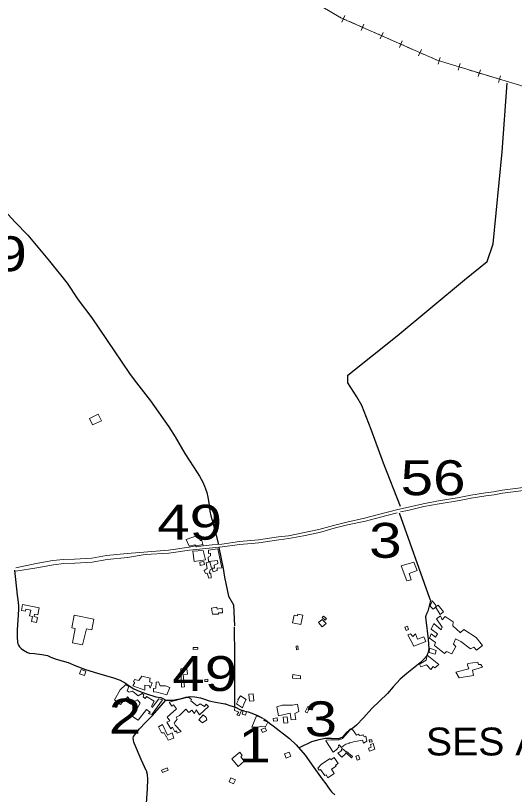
# Model space of a CAD drawing. Extents: x 476989 to 498418, y 4381813 to 4416555.
# Drawn here: x 486413 to 487128, y 4387137 to 4388253 of the extents above; entities that cross this region are included whole.
import ezdxf
from ezdxf.enums import TextEntityAlignment as Align

# ---------------------------------------------------------------- set-up
doc = ezdxf.new("R2010")
doc.units = 0
doc.header["$LTSCALE"] = 20
doc.linetypes.add('MEDIUM_DASHED', pattern=[4.5, 3, -1.5])
for name, color, linetype, lineweight in [('13', 7, 'Continuous', 13), ('34', 7, 'Continuous', 13), ('36', 7, 'Continuous', 13), ('47', 7, 'Continuous', 13), ('48', 7, 'MEDIUM_DASHED', 13), ('6', 7, 'Continuous', 25)]:
    doc.layers.add(name, color=color, linetype=linetype, lineweight=lineweight)
doc.layers.add('7', color=7, linetype='Continuous')

msp = doc.modelspace()

# ---------------------------------------------------------------- linework, layer by layer
at = {"layer": '34'}
for p, q in [((486884.69, 4388252.95), (486880.65, 4388243.8)), ((486891.82, 4388244.33), (486900.97, 4388240.29)), ((486905.53, 4388238.27), (486914.68, 4388234.23)), ((486912.12, 4388240.83), (486908.08, 4388231.68)), ((486919.25, 4388232.21), (486928.39, 4388228.17)), ((486932.96, 4388226.15), (486942.11, 4388222.11)), ((486939.55, 4388228.7), (486935.51, 4388219.55)), ((486946.68, 4388220.08), (486955.82, 4388216.04)), ((486960.39, 4388214.02), (486969.53, 4388209.98)), ((486966.98, 4388216.58), (486962.94, 4388207.43)), ((486974.11, 4388207.96), (486983.25, 4388203.92)), ((486987.82, 4388201.9), (486996.96, 4388197.86)), ((486994.41, 4388204.45), (486990.37, 4388195.3)), ((487001.54, 4388195.83), (487010.68, 4388191.79)), ((487021.4, 4388192.89), (487018.5, 4388183.32)), ((487029.52, 4388185.2), (487039.09, 4388182.29)), ((487043.86, 4388180.84), (487053.43, 4388177.94)), ((487050.1, 4388184.17), (487047.19, 4388174.6)), ((487058.22, 4388176.48), (487067.78, 4388173.58)), ((487072.56, 4388172.13), (487082.13, 4388169.22)), ((487078.8, 4388175.46), (487075.89, 4388165.89)), ((487086.91, 4388167.77), (487096.48, 4388164.86)), ((487101.25, 4388163.41), (487110.82, 4388160.51)), ((487107.49, 4388166.74), (487104.59, 4388157.17)), ((487115.61, 4388159.05), (487125.18, 4388156.15))]:
    msp.add_line(p, q, dxfattribs=at)
for points in [[(486520.9, 4388755.72), (486603, 4388633), (486612, 4388581), (486746, 4388393), (486776, 4388338), (486812, 4388290), (486879, 4388250), (487017, 4388189), (487152, 4388148), (487234, 4388140), (487360, 4387899), (487497, 4387717), (487531, 4387660), (487608, 4387440), (487634, 4387181), (487675, 4387065), (487547, 4387001), (487350, 4386921), (487175, 4386900), (487110, 4386912), (487380, 4386493), (487280.6, 4386441.97)], [(486878.15, 4388250.5), (486879, 4388250), (486887.25, 4388246.36)], [(487015.25, 4388189.77), (487017, 4388189), (487024.74, 4388186.65)]]:
    msp.add_lwpolyline(points, dxfattribs=at)
at = {"layer": '36'}
for points in [[(486964.24, 4387541.72), (486976.62, 4387544.44), (486997.64, 4387549.32), (487019.8, 4387553.44), (487049.13, 4387558.2), (487065.84, 4387561.49), (487086.71, 4387564.87), (487098.48, 4387566.27), (487110.55, 4387568.8), (487159.87, 4387575), (487190.84, 4387579.06), (487223.09, 4387583.7), (487249.79, 4387587.82), (487273.23, 4387590.72), (487282.06, 4387591.19), (487293.97, 4387593.33), (487302.49, 4387595.71), (487317.85, 4387602.66), (487349.41, 4387615.35), (487395.22, 4387635.1), (487449.89, 4387659.15), (487513.35, 4387686.84), (487513.66, 4387686.96)], [(486681.81, 4387493.08), (486694.64, 4387494.43), (486708.83, 4387495.72), (486733.93, 4387499.19), (486761.2, 4387501.8), (486789.75, 4387505.79), (486803.91, 4387507.68), (486824.62, 4387511.62), (486847.35, 4387516.42), (486868.27, 4387522.32), (486887.64, 4387527.27), (486913.13, 4387532.74), (486932.76, 4387537.91), (486960.47, 4387544.96), (486975.67, 4387548.51), (486996.79, 4387553.41), (487019.08, 4387557.56), (487048.39, 4387562.31), (487065.1, 4387565.6), (487086.13, 4387569.01), (487097.8, 4387570.4), (487109.95, 4387572.95), (487159.3, 4387579.14)], [(486598.9, 4387480.47), (486632.81, 4387482.84), (486662.41, 4387486.84), (486695.05, 4387490.27), (486709.31, 4387491.57), (486734.42, 4387495.04), (486761.69, 4387497.65), (486790.31, 4387501.65), (486804.58, 4387503.55), (486825.44, 4387507.52), (486848.35, 4387512.36), (486869.35, 4387518.28), (486888.6, 4387523.19), (486914.1, 4387528.67), (486933.81, 4387533.87), (486959.88, 4387540.27)], [(486632.38, 4387487), (486661.92, 4387490.99), (486681.28, 4387495)], [(486413.56, 4387461.76), (486442.85, 4387467.63), (486466.63, 4387471.94), (486482.05, 4387473.6), (486497.67, 4387474.12), (486522.37, 4387475.65), (486543.65, 4387479.24), (486573.11, 4387482.2), (486632.38, 4387487)], [(486413.64, 4387456.96), (486443.84, 4387461.83), (486467.47, 4387466.12), (486482.46, 4387467.73), (486497.95, 4387468.25), (486523.04, 4387469.8), (486544.43, 4387473.41), (486573.69, 4387476.35), (486598.9, 4387480.47)]]:
    msp.add_lwpolyline(points, dxfattribs=at)
at = {"layer": '47'}
for points in [[(486681.79, 4387493.07), (486672.16, 4387491.55), (486669.88, 4387494.66), (486662.05, 4387492.45), (486657.31, 4387501.97), (486675.11, 4387508.62), (486677.55, 4387500.93), (486679.72, 4387500.83)], [(486702.81, 4387488.86), (486689.51, 4387486.95), (486689.28, 4387481.93), (486692.44, 4387482.41), (486692.39, 4387478.88), (486688.91, 4387476.98), (486689.65, 4387470.82), (486702.2, 4387472.21), (486702.81, 4387467.63), (486697.75, 4387465.6), (486697.92, 4387461.17), (486693.79, 4387460.93), (486691.37, 4387470.42), (486686.02, 4387468.54), (486687.4, 4387460.65), (486683.39, 4387457.85), (486684.98, 4387453.7), (486687.83, 4387454.11), (486690.05, 4387446.65), (486693.36, 4387447.2), (486693.01, 4387453.96), (486690.46, 4387454.15), (486691.88, 4387458.93), (486694.82, 4387460.09), (486696.34, 4387455.94), (486701.85, 4387457.89), (486701.89, 4387461.04), (486708.65, 4387461.77)], [(486681.77, 4387486.46), (486685.26, 4387473.28), (486668.94, 4387470.89), (486666.9, 4387485.4)], [(486682.82, 4387470.77), (486676.87, 4387469.5), (486677.41, 4387464.84), (486683.66, 4387466.48)], [(486988.11, 4387457.61), (486976.94, 4387453.27), (486979.74, 4387444.23), (486973.64, 4387442.81), (486965.47, 4387464.47), (486983.7, 4387469.68)], [(487009.7, 4387414.31), (487006.96, 4387406.84), (487011.33, 4387402.58), (487015.65, 4387405.67), (487014.64, 4387408.39)], [(486423.14, 4387409.21), (486446.93, 4387404.29), (486444.89, 4387394.45), (486440.49, 4387395.32), (486439.77, 4387391.68), (486444.84, 4387390.63), (486443.34, 4387383.4), (486436.27, 4387384.85), (486437.68, 4387391.77), (486433.34, 4387392.62), (486435, 4387401.12), (486427.82, 4387402.49), (486427.27, 4387399.61), (486421.83, 4387400.62)], [(486693.57, 4387403.76), (486695.02, 4387395.26), (486703.65, 4387395.43), (486703.9, 4387397), (486709.38, 4387397.3), (486709.03, 4387403.98), (486701.95, 4387402.51), (486701.39, 4387405.29)], [(487014.75, 4387405.91), (487021.42, 4387394.48), (487025.9, 4387398.47), (487018.31, 4387407.96)], [(486509.27, 4387351.09), (486494.76, 4387353.93), (486498.79, 4387374.52), (486493.86, 4387375.47), (486497.34, 4387393.57), (486525.22, 4387388.19), (486522.26, 4387372.89), (486514.98, 4387374.26)], [(486821.62, 4387380.39), (486809.87, 4387382.65), (486811.99, 4387393.69), (486816.99, 4387392.71), (486817.49, 4387395.28), (486824.65, 4387393.85)], [(486852.49, 4387387.75), (486857.88, 4387381.59), (486852.48, 4387376.87), (486847.09, 4387383.03)], [(486856.38, 4387386.79), (486852.4, 4387390.34), (486854.28, 4387392.45), (486858.26, 4387388.9)], [(487081.64, 4387350.32), (487072.72, 4387361.63), (487055.18, 4387372.99), (487049.93, 4387368.41), (487049.87, 4387368.86), (487039.57, 4387378.61), (487039.66, 4387384.39), (487028.28, 4387391.83), (487024.09, 4387387.16), (487021.62, 4387392.6), (487016.01, 4387388.56), (487024.24, 4387376.66), (487022.69, 4387372.93), (487012.16, 4387382.01), (487008.44, 4387373.73), (487017.65, 4387367.07), (487014.8, 4387362.09), (487008.57, 4387367.2), (487006, 4387360.86), (487014.77, 4387354.81), (487012.98, 4387350.33), (487027.45, 4387338.79), (487030.26, 4387341.53), (487038.03, 4387338.57), (487043.8, 4387348.84), (487040.32, 4387352.34), (487043.13, 4387359.73), (487050.73, 4387356.09), (487064.68, 4387345.31), (487069.37, 4387347.95), (487073.37, 4387343.84)], [(486970.73, 4387376.37), (486972.49, 4387371.88), (486976.09, 4387373.29), (486974.33, 4387377.78)], [(487000.61, 4387356.21), (486983.33, 4387349.33), (486975.16, 4387365.73), (486978.78, 4387366.8), (486982.1, 4387363.38), (486986.06, 4387367.15), (486988.87, 4387359.23), (486998.08, 4387362.92), (486998.08, 4387362.92)], [(486674.26, 4387344.83), (486667.77, 4387344.47), (486667.62, 4387347.25), (486674.11, 4387347.61)], [(486817.5, 4387349.83), (486818.08, 4387344.44), (486815.47, 4387344.16), (486814.89, 4387349.55)], [(487014.08, 4387337.93), (487005.48, 4387340.08), (487006.17, 4387346.3), (487015.58, 4387343.24)], [(487019.27, 4387323), (487002.58, 4387336.67), (487001.35, 4387329.49), (486991.66, 4387323.47), (486993.71, 4387319.69), (487001.63, 4387322.5), (487007.76, 4387315.81), (487011.43, 4387320.26), (487013.8, 4387318.5)], [(487069.09, 4387307.28), (487048.56, 4387303.82), (487043.88, 4387312.22), (487062.18, 4387316.98), (487060.6, 4387321.96), (487060.63, 4387324.29), (487075.29, 4387326.33), (487076, 4387323.01), (487079.53, 4387323.26), (487081.65, 4387319.41), (487067.7, 4387314.8)], [(486506.97, 4387315.93), (486514.07, 4387313.45), (486511.87, 4387307.16), (486504.77, 4387309.64)], [(486650.75, 4387290.61), (486649.85, 4387316.81), (486657.48, 4387317.36), (486657.49, 4387317.1), (486658.65, 4387317.22), (486659.5, 4387308.99), (486653.39, 4387308.4), (486655.04, 4387291.23)], [(486598.24, 4387286.11), (486581.15, 4387292.66), (486583.99, 4387297.05), (486582.13, 4387298.2), (486583.38, 4387301.63), (486589.66, 4387300.12), (486594.18, 4387306.58), (486605.77, 4387303.64), (486604.94, 4387298.1), (486608.67, 4387296.99), (486605.93, 4387289.23), (486604.64, 4387293.07), (486598.12, 4387293.39)], [(486629.96, 4387279.81), (486615.6, 4387283.24), (486610.81, 4387283.68), (486610.73, 4387288.64), (486613.96, 4387288.96), (486614.39, 4387297.74), (486618.07, 4387298.21), (486620.09, 4387292.55), (486627.82, 4387292.37), (486634.01, 4387290.1)], [(486688.69, 4387298.92), (486684.37, 4387298.62), (486684.15, 4387301.69), (486688.47, 4387301.99)], [(486810.46, 4387308.66), (486821.17, 4387306.93), (486821.18, 4387302.65), (486809.94, 4387303.72)], [(486608.39, 4387251.38), (486623.48, 4387272.54), (486618.24, 4387273.82), (486608.76, 4387261.5), (486607.66, 4387263.32), (486611.75, 4387270.61), (486600.74, 4387277.3), (486598.59, 4387274.33), (486596.07, 4387276.61), (486596.94, 4387279.6), (486594.57, 4387281.59), (486588.97, 4387278.37), (486580.44, 4387285.09), (486575.83, 4387283.21), (486573.24, 4387285.5), (486575.65, 4387291.69), (486570.74, 4387294.09), (486562.91, 4387286.99), (486555.12, 4387272.32), (486563.66, 4387265.97), (486569.91, 4387273.24), (486570.72, 4387272.18), (486573.71, 4387276.63), (486576.14, 4387273.45), (486573.68, 4387269.36), (486578.29, 4387266.36), (486582.32, 4387269.46), (486588.06, 4387272.38), (486591.67, 4387267.67), (486580.81, 4387248.47), (486588.92, 4387243.48), (486600.69, 4387258.61), (486605.82, 4387254.94), (486603.39, 4387252.72)], [(486689.6, 4387262.97), (486676.74, 4387250.7), (486672.05, 4387258.04), (486669.34, 4387252.83), (486665.59, 4387257.68), (486661.19, 4387254.3), (486657.12, 4387258.86), (486647.85, 4387250.21), (486643.31, 4387247.5), (486643.67, 4387246.67), (486644.47, 4387244.86), (486640.18, 4387238.76), (486641.79, 4387236.04), (486650.14, 4387226.99), (486644.78, 4387224.67), (486643.48, 4387227.99), (486641.13, 4387226.44), (486638.15, 4387233.39), (486635.34, 4387231.11), (486630, 4387240.34), (486634.08, 4387242.3), (486630.55, 4387247.83), (486643.47, 4387259.35), (486639.43, 4387265.26), (486636.78, 4387263.35), (486633.33, 4387269.1), (486658.49, 4387275.95), (486661.12, 4387275.83), (486665.28, 4387272.85), (486664.05, 4387271.14), (486673.33, 4387263.73), (486677.42, 4387266.74), (486683.6, 4387262.9), (486686.35, 4387266.39)], [(486738.05, 4387261.15), (486729.72, 4387266.75), (486732.19, 4387271.44), (486731.46, 4387272.57), (486735.21, 4387278.07), (486743.24, 4387273.08), (486740.47, 4387267.87)], [(486753.34, 4387281.26), (486754.19, 4387271.17), (486748.31, 4387270.68), (486747.46, 4387280.77)], [(486806.59, 4387253.19), (486789.73, 4387249.68), (486787.14, 4387262.62), (486795.2, 4387264.76), (486809.98, 4387264.77), (486817.05, 4387266.02), (486818.71, 4387255.57), (486813.04, 4387252.65), (486814.34, 4387244.15), (486807.73, 4387243.57)], [(486727.03, 4387262.13), (486736.71, 4387257.19), (486733.6, 4387249.28), (486730.17, 4387250.98), (486732.78, 4387254.7), (486726.51, 4387257.04)], [(486742.69, 4387250.35), (486737.52, 4387251.81), (486738.96, 4387256.93), (486744.13, 4387255.47)], [(486834.4, 4387261.64), (486830.63, 4387253.99), (486828.15, 4387255.21), (486831.92, 4387262.86)], [(486681.92, 4387250.7), (486675.89, 4387243.58), (486681.01, 4387239.46), (486687.14, 4387243.57), (486685.99, 4387247.04)], [(486758.36, 4387249.45), (486769.41, 4387245.09), (486768.92, 4387242.62), (486774.67, 4387240.36), (486771.04, 4387233.59), (486766.11, 4387234.86), (486759.93, 4387233.15), (486751.53, 4387233.27)], [(486788.28, 4387242.57), (486782.54, 4387241.81), (486782.02, 4387245.74), (486787.76, 4387246.5)], [(486797.31, 4387238.84), (486796.27, 4387247.46), (486802.02, 4387248.15), (486803.06, 4387239.53)], [(486617.97, 4387233.61), (486622.2, 4387225.07), (486626.1, 4387225.01), (486628.51, 4387220.4), (486628.66, 4387220.4), (486631.73, 4387214.42), (486640.02, 4387217.53), (486637.28, 4387225.22), (486630.7, 4387221.57), (486623.57, 4387236.9)], [(486770.8, 4387232.09), (486765.12, 4387229.83), (486766.8, 4387225.62), (486772.48, 4387227.88)], [(486868.22, 4387197.45), (486857.35, 4387213.44), (486858.19, 4387214.78), (486864.88, 4387215.21), (486871.55, 4387215.12), (486876.13, 4387215.27), (486876.51, 4387215.34), (486878.54, 4387215.84), (486879.44, 4387216.05), (486881.26, 4387217), (486892.46, 4387229.22), (486895.77, 4387229.7), (486901.66, 4387221.81), (486904.08, 4387223.13), (486905.64, 4387221.53), (486908.56, 4387221.56), (486910.07, 4387221.92), (486911.05, 4387222.43), (486912.36, 4387219.63), (486914.7, 4387220.2), (486916.17, 4387213.05), (486911.56, 4387210.56), (486910.04, 4387214.71), (486896.95, 4387212.12), (486892.2, 4387210.84), (486891.52, 4387210.63), (486890.92, 4387210.56), (486887.98, 4387209.48), (486886.39, 4387208.75), (486883.29, 4387206.99), (486879.8, 4387203.89), (486876.55, 4387208.06), (486875.64, 4387207.33), (486876.21, 4387204.77), (486873.77, 4387202.48), (486874.07, 4387202.25)], [(486920.17, 4387198.96), (486927.86, 4387201.55), (486925.07, 4387209.82), (486921.31, 4387208.57), (486922.6, 4387204.66), (486918.63, 4387203.36)], [(486919.83, 4387211.95), (486923.66, 4387212.18), (486923.48, 4387215.12), (486919.65, 4387214.89)], [(486740.48, 4387184.58), (486735.69, 4387190.72), (486737.89, 4387192.57), (486734.51, 4387197.57), (486722.74, 4387187.98), (486732.04, 4387176.89)], [(486804.97, 4387197.53), (486807.29, 4387191.65), (486800.49, 4387188.97), (486798.17, 4387194.85)], [(486874.8, 4387195.93), (486880.65, 4387190.07), (486884.2, 4387193.62), (486884.1, 4387193.71), (486886.41, 4387196.28), (486894.11, 4387189.35), (486895.63, 4387191.04), (486887.19, 4387198.61), (486886.47, 4387197.82), (486881.06, 4387202.73), (486879.38, 4387200.88), (486880.32, 4387200.01)], [(486851.24, 4387180.36), (486863.52, 4387188.59), (486864.92, 4387186.48), (486869.68, 4387189.65), (486875.18, 4387181.39), (486871.42, 4387178.9), (486872.43, 4387177.36), (486865.55, 4387172.85), (486869.53, 4387166.76), (486860.55, 4387160.89), (486857.85, 4387165.01), (486855.95, 4387163.76), (486850.02, 4387172.75), (486847.96, 4387171.41), (486845.86, 4387174.63)], [(486900.71, 4387191.74), (486902.59, 4387186.12), (486906.35, 4387187.38), (486904.47, 4387193)], [(486630.19, 4387175.2), (486622.2, 4387171.67), (486623.78, 4387168.09), (486631.77, 4387171.62)], [(486725.45, 4387151.85), (486718.86, 4387154.86), (486721.52, 4387160.69), (486728.11, 4387157.68)]]:
    msp.add_lwpolyline(points, close=True, dxfattribs=at)
at = {"layer": '48'}
msp.add_lwpolyline([(486531.5, 4387681.91), (486518.99, 4387675.77), (486523.62, 4387666.34), (486536.13, 4387672.48)], close=True, dxfattribs=at)
at = {"layer": '6'}
for p, q in [((486704.26, 4387490.71), (486710.68, 4387460.5)), ((486815.26, 4387207.87), (486827.96, 4387192.96))]:
    msp.add_line(p, q, dxfattribs=at)
for points in [[(486964.25, 4387549.39), (486940.33, 4387611.72), (486922.4, 4387659.67), (486909.24, 4387694.44), (486902.07, 4387706.43), (486888.91, 4387726.81), (486888.91, 4387737.59), (486959.47, 4387793.94), (487056.33, 4387874.25), (487088.62, 4387900.63), (487096.99, 4387925.8), (487110.14, 4388057.67), (487117.32, 4388155.96)], [(486383.88, 4387990.09), (486386.63, 4387987.64), (486397.48, 4387973.58), (486412.62, 4387957.15), (486430.7, 4387938.38), (486461.98, 4387901.19), (486486.91, 4387869.73), (486502.64, 4387845.57), (486522.26, 4387819.72), (486543.26, 4387788.72)], [(486543.26, 4387788.72), (486576.47, 4387740.24), (486582.99, 4387730.92)], [(486583.19, 4387730.92), (486606.29, 4387700.79), (486632.5, 4387663.69), (486641.84, 4387649.12), (486655.83, 4387625.66), (486668.23, 4387606.21), (486676.45, 4387592.72), (486681.31, 4387584.19), (486683.88, 4387578.47), (486685.34, 4387574.6), (486687.31, 4387569.4), (486688.59, 4387562.92), (486690.24, 4387551.76), (486691.38, 4387543), (486693, 4387536.2), (486695.64, 4387526.49), (486698.83, 4387513.46), (486703.98, 4387495.26)], [(486962.42, 4387540.27), (487005.9, 4387418.31), (487007.28, 4387414.58), (487005.99, 4387409.23), (487003.38, 4387399.43), (487002.36, 4387396.43), (487001.65, 4387395.16), (487001.2, 4387394.35), (487000.89, 4387393.54), (487000.51, 4387392.28), (487000.42, 4387391.62), (487000.4, 4387390.21), (487000.5, 4387386.99), (487003.86, 4387359.55), (487005.09, 4387345.63), (487004.67, 4387343.51), (487003.95, 4387340.29), (487003.31, 4387338.25), (487002, 4387335.41), (486997.18, 4387330.36), (486992.38, 4387325.46), (486973.32, 4387310.35), (486963.98, 4387301.94), (486954.08, 4387291.21), (486945.75, 4387281.5), (486923.23, 4387259.91), (486911.64, 4387246.42), (486901.28, 4387235.99), (486896.18, 4387231.77)], [(486411.61, 4387458.24), (486415.3, 4387422.43), (486416.72, 4387412.28), (486417.46, 4387406.2), (486417.33, 4387402.54), (486416.99, 4387394.22), (486415.48, 4387372.78), (486415.33, 4387362.26), (486415.97, 4387354.88), (486416.47, 4387352.52), (486417.3, 4387350.83), (486419.05, 4387348.22), (486421.07, 4387345.87), (486425.78, 4387342.62), (486428.02, 4387341.52), (486430.46, 4387340.43), (486433.13, 4387339.5), (486440.42, 4387338.79), (486450.6, 4387337.38), (486458.96, 4387335.83), (486461.08, 4387334.99), (486463.79, 4387333.66), (486471.49, 4387330.85), (486488.68, 4387325.72), (486499.63, 4387321.14), (486513.37, 4387315.84), (486530.49, 4387310.87), (486553.35, 4387303.94), (486562.89, 4387300.43), (486567.35, 4387298.34), (486569.2, 4387297.27), (486570.62, 4387296.51), (486572.68, 4387295.06), (486574.6, 4387293.23)], [(486710.68, 4387460.5), (486712.57, 4387448.03), (486718.24, 4387420.84), (486725.43, 4387408.38), (486726.56, 4387378.54)], [(486726.16, 4387377.24), (486726.32, 4387377.08), (486726.91, 4387334.91), (486726.62, 4387299.12), (486726.56, 4387263.13)], [(486574.6, 4387293.23), (486582.62, 4387288.43), (486590.34, 4387284.71), (486600.7, 4387280.94), (486613.89, 4387276.82), (486621.12, 4387275.61), (486624.29, 4387274.43), (486628.31, 4387271.95)], [(486628.9, 4387272.11), (486638.48, 4387271.93), (486650.95, 4387274.12), (486657.1, 4387276.06), (486663.18, 4387277.02), (486669.74, 4387276.52), (486678.26, 4387275.12), (486683.99, 4387273.21), (486690.31, 4387270.94), (486699.7, 4387269.09), (486710.54, 4387267.04), (486713.02, 4387266.69), (486713.92, 4387266.53), (486714.59, 4387266.16), (486720.23, 4387264.18), (486728.33, 4387261.91), (486734.39, 4387258.65), (486740.44, 4387256.54)], [(486600.42, 4387116.95), (486602.31, 4387144.73), (486602.51, 4387158.7), (486602.12, 4387165.54), (486600.59, 4387170.92), (486600.46, 4387171.2), (486593.21, 4387186.85), (486583.65, 4387209.28), (486582.41, 4387211.77), (486581.87, 4387214.56), (486581.79, 4387217.25), (486582.34, 4387219.68), (486590.6, 4387230.84), (486599.3, 4387239.8), (486609.37, 4387250.12), (486628.41, 4387272.11)], [(486741.42, 4387256.25), (486746.47, 4387255.19), (486749.97, 4387254.04), (486758.67, 4387250.65), (486765.42, 4387247.08), (486766.97, 4387246.15)], [(486769.4, 4387244.7), (486771.63, 4387243.37), (486777.04, 4387239.11), (486782.02, 4387235.2), (486805.26, 4387217.13), (486815.26, 4387207.87)], [(486896.18, 4387231.77), (486891.75, 4387230.01), (486886.29, 4387224.76), (486881.42, 4387219.11), (486875.57, 4387216.78), (486865.44, 4387217.17), (486857.06, 4387216.97), (486847.71, 4387215.22), (486837.18, 4387212.11), (486819.25, 4387203.55)], [(486827.96, 4387192.96), (486840.26, 4387175.44), (486852.39, 4387158.74), (486857.7, 4387152), (486860.52, 4387147.59), (486862.96, 4387144.22), (486865.82, 4387140.44), (486870.56, 4387136.44)]]:
    msp.add_lwpolyline(points, dxfattribs=at)

# ---------------------------------------------------------------- texts
at = {"layer": '13', "width": 1.25}
for s, p in [('3', (486942.77, 4387475.99)), ('49', (486684.21, 4387285.09)), ('2', (486570.08, 4387224.13)), ('3', (486850.42, 4387220.28))]:
    msp.add_text(s, height=50, dxfattribs=at).set_placement(p, align=Align.CENTER)
at = {"layer": '6', "width": 1.25}
for s, p in [('49', (486382.99, 4387886.71)), ('56', (487011.09, 4387565.71)), ('49', (486662.47, 4387501.92)), ('1', (486755.68, 4387182.92))]:
    msp.add_text(s, height=50, dxfattribs=at).set_placement(p, align=Align.CENTER)
at = {"layer": '7', "width": 1.05}
msp.add_text('SES ALQUERIES', height=40, dxfattribs=at).set_placement((487225.58, 4387192.7), align=Align.CENTER)

doc.saveas('drawing.dxf')
